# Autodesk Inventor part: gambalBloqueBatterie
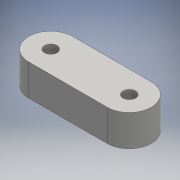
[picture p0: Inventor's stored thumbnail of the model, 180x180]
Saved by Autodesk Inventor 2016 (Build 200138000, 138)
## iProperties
Created: 2016-01
Part Number: gambalBloqueBatterie
Material: Generic
Document SubType Name: Modeling
Designer: Peter
Density: 1 g/cm^3
Appearance: Default
Author: Peter
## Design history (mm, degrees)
sketch "Esquisse1"
  geometry: L1 (12.5, 32.5)-(-12.5, 32.5); L2 (-12.5, 32.5)-(12.5, 32.5); L3 (-12.5, 25.5)-(12.5, 25.5); L4 (12.5, 39.5)-(-12.5, 39.5); C1 r 2 at (12.5, 32.5); C2 r 2 at (-12.5, 32.5); A1 r 7 centre (-12.5, 32.5) between (-12.5, 39.5) and (-12.5, 25.5); A2 r 7 centre (12.5, 32.5) between (12.5, 25.5) and (12.5, 39.5); 1 further point
  constraints: 10 end point, 4 centre point, 4 point on circle, 4 tangent, 1 equal radius, 1 horizontal, 1 midpoint, 1 parallel
  dimensions: "d3" = 25 distance of L1.start L1.end; "d4" = 5 radial gap between concentric circles of A2 C1; "d5" = 4 diameter of C1
extrude "Extrusion1" new body sketch "Esquisse1" distance "d6" = 10; taper "d7" = 0 deg
node "Solide1"
